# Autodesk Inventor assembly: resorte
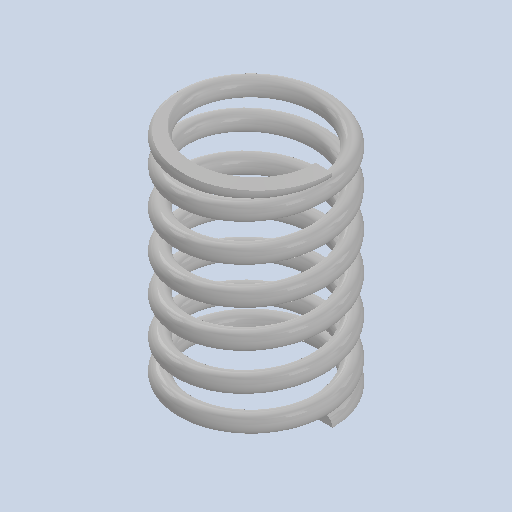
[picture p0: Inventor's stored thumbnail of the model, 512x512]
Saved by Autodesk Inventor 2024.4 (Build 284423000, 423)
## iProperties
Created: 2025-06
Part Number: resorte
Document SubType Name: Assembly
Designer: AdminForWorker
Title: resorte v2
Author: AdminForWorker
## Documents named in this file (2)
- c:\worker\convert-fusion-r02-cosv3\tmp\job-1\269\temp\files\84dad1ff-1950-46bc-935e-e3958f356a90\c2720c51-7475-4a6d-964c-0bdbd260d7d9.iam
- c:\worker\convert-fusion-r02-cosv3\tmp\job-1\269\temp\files\84dad1ff-1950-46bc-935e-e3958f356a90\94125K631_Compression Springs.ipt
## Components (1 placed, 1 different names)
1. 94125K631_Compression Springs:1
